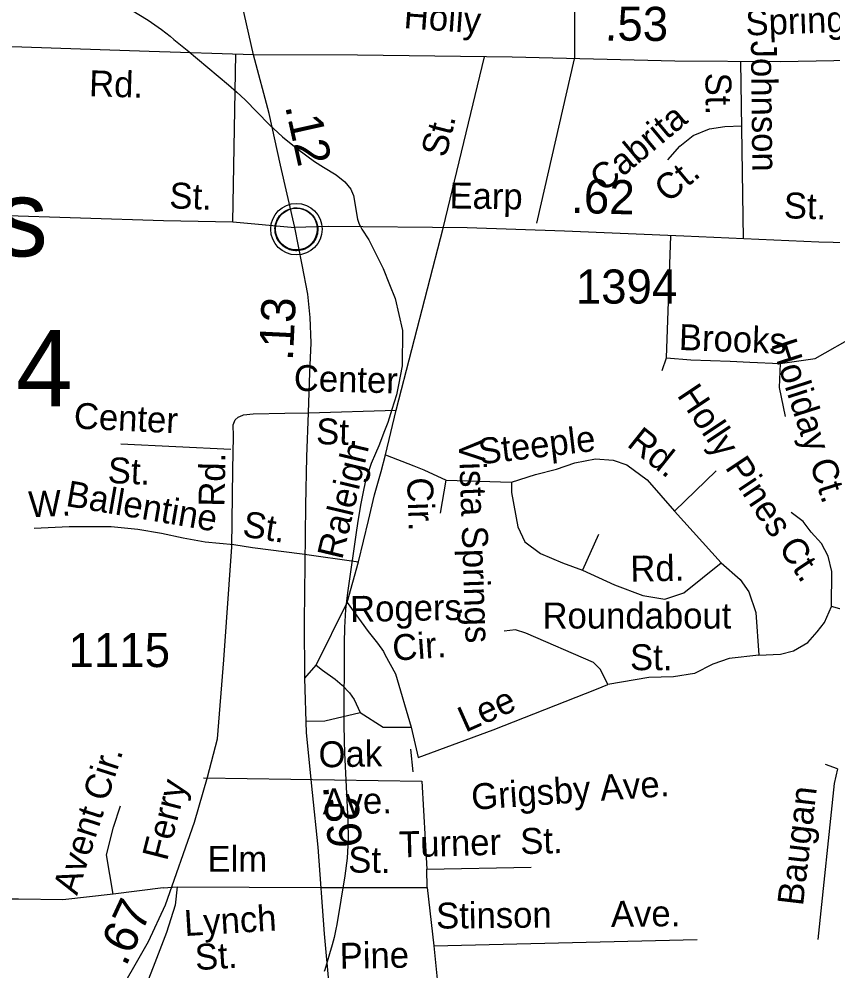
# Model space of a CAD drawing. Extents: x 2001466 to 2224147, y 644118 to 847247.
# Drawn here: x 2048372 to 2051357, y 689942 to 693432 of the extents above; entities that cross this region are included whole.
import ezdxf

# ---------------------------------------------------------------- set-up
doc = ezdxf.new("R2010")
doc.units = 0
for name, color, linetype in [('Exist Civil Demographics City Label', 7, 'Continuous'), ('Exist Civil Demographics Community CELL', 7, 'Continuous'), ('Exist Hydrographic Misc Water Feature', 7, 'Continuous'), ('Exist Road Non-System Type 51', 7, 'Continuous'), ('Exist Road Non-System Type 51 Label', 7, 'Continuous'), ('Exist Road Primary NC Attributed', 7, 'Continuous'), ('Exist Road Primary NC Service Mileage Hundredths English Label', 7, 'Continuous'), ('Exist Road Secondary Mileage Hundredths English Label', 7, 'Continuous'), ('Exist Road Secondary Type 51 Attributed', 7, 'Continuous'), ('Exist Road Secondary Type 51 Label', 7, 'Continuous'), ('Exist Road Secondary Type 51 Number Label', 7, 'Continuous')]:
    doc.layers.add(name, color=color, linetype=linetype)

msp = doc.modelspace()

# ---------------------------------------------------------------- linework, layer by layer
at = {"layer": 'Exist Civil Demographics Community CELL'}
msp.add_lwpolyline([(2049311.9, 692674.2), (2049312.9, 692679.8), (2049314.7, 692686.4), (2049317.6, 692693.6), (2049320.5, 692699.3), (2049323.9, 692705.1), (2049327.6, 692710.2), (2049331.6, 692714.6), (2049336.2, 692719.2), (2049341.7, 692723.7), (2049347.1, 692727.4), (2049352, 692730.3), (2049357.1, 692732.7), (2049362.5, 692735), (2049368.2, 692736.8), (2049372.5, 692738), (2049377.3, 692738.7), (2049381.5, 692739.5), (2049387.8, 692739.7), (2049392.3, 692739.6), (2049397.9, 692739.3), (2049402.8, 692738.6), (2049407.7, 692737.6), (2049412.8, 692736.2), (2049417.9, 692734.3), (2049424.6, 692731.4), (2049430.8, 692727.9), (2049435.9, 692724.3), (2049441.1, 692720.3), (2049444.4, 692717.2), (2049448.5, 692712.8), (2049452.4, 692708.1), (2049455.4, 692703.5), (2049458.6, 692698.5), (2049461, 692693.3), (2049463.1, 692688.3), (2049464.6, 692683.3), (2049465.9, 692678.7), (2049467, 692672.7), (2049467.6, 692668), (2049467.9, 692662), (2049467.7, 692656.2), (2049467.1, 692650.5), (2049466.2, 692645), (2049464.5, 692638.9), (2049462.7, 692633), (2049460.4, 692627.9), (2049457.2, 692621.9), (2049453.9, 692616.6), (2049450.5, 692611.9), (2049446.3, 692607.2), (2049441, 692602.2), (2049435.9, 692598.1), (2049430.9, 692594.7), (2049426.6, 692592.2), (2049419.8, 692588.9), (2049412.6, 692586.2), (2049406.7, 692584.7), (2049400.1, 692583.4), (2049395.7, 692583), (2049391.2, 692582.7), (2049385.6, 692582.7), (2049381.3, 692583.1), (2049375.7, 692583.9), (2049369.8, 692585.2), (2049365.2, 692586.5), (2049360, 692588.3), (2049355.4, 692590.3), (2049351.5, 692592.6), (2049344.7, 692596.6), (2049339.1, 692600.9), (2049334.2, 692605.4), (2049329.7, 692610.3), (2049326.6, 692614.2), (2049323.6, 692618.4), (2049319.5, 692625.5), (2049317.8, 692629), (2049316, 692633.1), (2049313.5, 692641.3), (2049311.9, 692648.3), (2049311.2, 692653.5), (2049310.9, 692659.8), (2049310.8, 692664.5), (2049311.4, 692670.9)], close=True, dxfattribs=at)
for centre, radius in [((2049389.5, 692661.8), 94.3), ((2049389.3, 692662.1), 76.7)]:
    msp.add_circle(centre, radius, dxfattribs=at)
at = {"layer": 'Exist Hydrographic Misc Water Feature'}
for p, q in [((2048783.2, 693465.6), (2048846.2, 693428.1)), ((2049567.1, 692835.3), (2049589.1, 692808.5)), ((2049589.1, 692808.5), (2049591.5, 692802.2)), ((2049589.1, 692808.5), (2049591.5, 692802.2)), ((2049493.1, 689947), (2049491.1, 689940.2))]:
    msp.add_line(p, q, dxfattribs=at)
for points in [[(2048846.2, 693428.1), (2048895.2, 693393.4), (2048926.1, 693368.7)], [(2048846.2, 693428.1), (2048895.2, 693393.4), (2048926.1, 693368.7)], [(2048926.1, 693368.7), (2048940.3, 693357.4), (2048988.3, 693317.4)], [(2048926.1, 693368.7), (2048940.3, 693357.4), (2048988.3, 693317.4)], [(2048988.3, 693317.4), (2049140.2, 693190.8), (2049170.6, 693163.6)], [(2048988.3, 693317.4), (2049140.2, 693190.8), (2049170.6, 693163.6)], [(2049170.6, 693163.6), (2049202.1, 693135.3), (2049290.1, 693045.7), (2049338.1, 693000.7), (2049394.1, 692954.5), (2049455.2, 692910.4), (2049488.4, 692889.6)], [(2049170.6, 693163.6), (2049202.1, 693135.3), (2049290.1, 693045.7), (2049338.1, 693000.7), (2049394.1, 692954.5), (2049455.2, 692910.4), (2049488.4, 692889.6)], [(2049488.4, 692889.6), (2049535.4, 692860.4), (2049567.1, 692835.3)], [(2049488.4, 692889.6), (2049535.4, 692860.4), (2049567.1, 692835.3)], [(2049591.5, 692802.2), (2049598.1, 692785.2), (2049613.1, 692698.6), (2049620, 692680.1), (2049623.9, 692672)], [(2049591.5, 692802.2), (2049598.1, 692785.2), (2049613.1, 692698.6), (2049620, 692680.1), (2049623.9, 692672)], [(2049623.9, 692672), (2049629.3, 692661.2), (2049655.1, 692622.6), (2049708, 692517), (2049730.8, 692459.1)], [(2049623.9, 692672), (2049629.3, 692661.2), (2049655.1, 692622.6), (2049708, 692517), (2049730.8, 692459.1)], [(2049730.8, 692459.1), (2049750.9, 692407.5), (2049778.1, 692289.8), (2049777.1, 692160.9), (2049763.4, 692090.5)], [(2049730.8, 692459.1), (2049750.9, 692407.5), (2049778.1, 692289.8), (2049777.1, 692160.9), (2049763.4, 692090.5)], [(2049763.4, 692090.5), (2049756.2, 692054.1), (2049739.8, 692000.8)], [(2049763.4, 692090.5), (2049756.2, 692054.1), (2049739.8, 692000.8)], [(2049739.8, 692000.8), (2049725, 691953.4), (2049712.9, 691922.8)], [(2049739.8, 692000.8), (2049725, 691953.4), (2049712.9, 691922.8)], [(2049712.9, 691922.8), (2049691, 691867), (2049678.9, 691839.4)], [(2049712.9, 691922.8), (2049691, 691867), (2049678.9, 691839.4)], [(2049678.9, 691839.4), (2049662.9, 691803), (2049643, 691738.9), (2049637.1, 691710.9)], [(2049678.9, 691839.4), (2049662.9, 691803), (2049643, 691738.9), (2049637.1, 691710.9)], [(2049637.1, 691710.9), (2049624.3, 691650.3), (2049613.3, 691582.9)], [(2049637.1, 691710.9), (2049624.3, 691650.3), (2049613.3, 691582.9)], [(2049613.3, 691582.9), (2049608.1, 691550.2), (2049576.2, 691328), (2049569, 691267.3)], [(2049613.3, 691582.9), (2049608.1, 691550.2), (2049576.2, 691328), (2049569, 691267.3)], [(2049569, 691267.3), (2049565.3, 691201.4), (2049564.1, 691143.5)], [(2049569, 691267.3), (2049565.3, 691201.4), (2049564.1, 691143.5)], [(2049564.1, 691143.5), (2049563, 690846.2), (2049564.3, 690786.5)], [(2049564.1, 691143.5), (2049563, 690846.2), (2049564.3, 690786.5)], [(2049564.3, 690786.5), (2049565.1, 690742.1), (2049578, 690493.2), (2049579, 690425.2), (2049575.1, 690355.9)], [(2049564.3, 690786.5), (2049565.1, 690742.1), (2049578, 690493.2), (2049579, 690425.2), (2049575.1, 690355.9)], [(2049575.1, 690355.9), (2049567.1, 690290.5), (2049537, 690112.1), (2049533.9, 690095.5)], [(2049575.1, 690355.9), (2049567.1, 690290.5), (2049537, 690112.1), (2049533.9, 690095.5)], [(2049533.9, 690095.5), (2049527.8, 690064.4), (2049520.4, 690038.2)], [(2049533.9, 690095.5), (2049527.8, 690064.4), (2049520.4, 690038.2)], [(2049520.4, 690038.2), (2049511.2, 690005.3), (2049493.1, 689947)], [(2049520.4, 690038.2), (2049511.2, 690005.3), (2049493.1, 689947)]]:
    msp.add_lwpolyline(points, dxfattribs=at)
at = {"layer": 'Exist Road Non-System Type 51'}
for p, q in [((2049155.7, 692688.3), (2049167.2, 693302.7)), ((2049927, 692665.2), (2050078.9, 693293.6)), ((2050270.5, 692684), (2050409.1, 693285.9)), ((2051028.9, 692626.3), (2051019.1, 693276.2)), ((2048200.1, 692715.7), (2048901.7, 692693.5)), ((2048901.7, 692693.5), (2049155.7, 692688.3)), ((2049155.7, 692688.3), (2049383.7, 692667.9)), ((2049755, 691998.3), (2049927, 692665.2)), ((2050745.8, 692189.6), (2050762.5, 692637.8)), ((2050730.3, 692143.2), (2050745.8, 692189.6)), ((2049433.8, 691988.7), (2049755, 691998.3)), ((2049715.6, 691834), (2049755, 691998.3)), ((2049148.4, 691854.4), (2048745.6, 691873.6)), ((2050928.8, 691775.5), (2050776, 691627.8)), ((2049918.2, 691620.9), (2049938.8, 691741.2)), ((2049938.8, 691741.2), (2050177.5, 691734.3)), ((2050776, 691627.8), (2050947.3, 691438.8)), ((2050496.8, 691541.9), (2050438.4, 691411.3)), ((2049054.7, 691515), (2049160, 691506.1)), ((2049411, 691471.5), (2049616.6, 691442.5)), ((2049575.5, 691293.6), (2049616.6, 691442.5)), ((2049462.2, 691063.4), (2049575.5, 691293.6)), ((2049420.1, 691015.9), (2049462.2, 691063.4)), ((2049809.7, 690836.6), (2049835.4, 690724.9)), ((2049817.9, 690672.3), (2049809, 690755.4)), ((2049049, 690650.3), (2049849.5, 690638.4)), ((2049849.5, 690638.4), (2049867.2, 690315)), ((2049867.2, 690315), (2050250.2, 690322.3)), ((2049869, 690248.6), (2049867.2, 690315)), ((2048901.1, 690247.5), (2048717.2, 690224.4)), ((2048901.1, 690247.5), (2048951.8, 690250.4)), ((2048951.8, 690250.4), (2049480.6, 690248.6)), ((2049480.6, 690248.6), (2049869, 690248.6)), ((2049869, 690248.6), (2049892.7, 690035)), ((2049892.7, 690035), (2050858.8, 690057.9)), ((2049892.7, 690035), (2049907, 689900.5))]:
    msp.add_line(p, q, dxfattribs=at)
for points in [[(2050407.2, 693733.7), (2050409.1, 693285.9)], [(2050750.9, 692916), (2050795.6, 692965.8), (2050843.6, 693005.3), (2050903.7, 693029.4), (2050960.4, 693038), (2051022.7, 693040.2)], [(2051163, 692169), (2051291.8, 692187.9), (2051446.3, 692275.5)], [(2050745.8, 692189.6), (2050835.1, 692182.7), (2050979.3, 692177.6), (2051051.4, 692174.1), (2051163, 692169)], [(2051163, 692169), (2051158.9, 692081.2), (2051181.2, 691974.7)], [(2049195.7, 691980.9), (2049230.4, 691984.2), (2049347.5, 691986.6), (2049433.8, 691988.7)], [(2049616.6, 691442.5), (2049654.3, 691593.2), (2049676.1, 691688.1), (2049700.2, 691773.8), (2049715.6, 691834)], [(2049715.6, 691834), (2049820.3, 691794.4), (2049856.4, 691779), (2049938.8, 691741.2)], [(2050177.5, 691734.3), (2050265.7, 691761.8), (2050343, 691782.4), (2050409.9, 691804.8), (2050485.5, 691820.2), (2050550.7, 691815.1), (2050600.5, 691797.9), (2050675.7, 691743.2), (2050776, 691627.8)], [(2050177.5, 691734.3), (2050178.2, 691696.5), (2050201.5, 691571.1), (2050227.3, 691516.1), (2050283.9, 691473.2), (2050364.6, 691438.8), (2050438.4, 691411.3)], [(2051350.7, 691278), (2051352.9, 691406.2), (2051339.2, 691462.9), (2051315.1, 691509.6), (2051277.3, 691550.5), (2051246.8, 691589.7), (2051203.5, 691622.6)], [(2048428.5, 691565.5), (2048556.1, 691571.4), (2048710.4, 691571.4), (2048808.3, 691562.5), (2048894.4, 691547.6), (2048974.5, 691529.8), (2049054.7, 691515)], [(2049160, 691506.1), (2049228.5, 691494.7), (2049411, 691471.5)], [(2051603.6, 691468), (2051614.8, 691367.1), (2051644.8, 691232.6), (2051548.6, 691224), (2051350.7, 691278)], [(2050438.4, 691411.3), (2050555.2, 691358.1), (2050659.9, 691318.5), (2050740.6, 691304.8), (2050809.3, 691328.8), (2050947.3, 691438.8)], [(2050947.3, 691438.8), (2051016, 691376.9), (2051048.6, 691332.3), (2051074.4, 691256.5), (2051084.7, 691100.2)], [(2049575.5, 691293.6), (2049652.8, 691187.1), (2049687.1, 691144.2), (2049708.9, 691113.7)], [(2051265, 691146.6), (2051299.3, 691186.1), (2051325.1, 691220.4), (2051350.7, 691278)], [(2050531.8, 690993), (2050504.6, 691047.9), (2050478.1, 691072.9), (2050231.1, 691180.8), (2050192.1, 691193.3), (2050151.4, 691188.6)], [(2051084.7, 691100.2), (2051163.7, 691103.6), (2051211.8, 691115.6), (2051265, 691146.6)], [(2049708.9, 691113.7), (2049714, 691102.8), (2049752.6, 691031.6), (2049809.7, 690836.6)], [(2051084.7, 691100.2), (2050976.5, 691087.5), (2050916.4, 691066.8), (2050849.5, 691032.5), (2050772.2, 691020.4), (2050681.2, 691018.7), (2050531.8, 690993)], [(2049462.2, 691063.4), (2049484.5, 691044.5), (2049530.9, 691011.9), (2049556.6, 690989.5)], [(2049556.6, 690989.5), (2049584.1, 690962), (2049601.3, 690938), (2049623.6, 690889.9)], [(2049835.4, 690724.9), (2050110.2, 690826.3), (2050489.6, 690975.8), (2050531.8, 690993)], [(2049425.1, 690857.6), (2049493.1, 690858.9), (2049623.6, 690889.9)], [(2049623.6, 690889.9), (2049707.7, 690836.6), (2049809.7, 690836.6)], [(2051373.6, 690683.1), (2051329.8, 690698.7)], [(2051373.6, 690683.1), (2051361.1, 690629.9), (2051301.7, 690057.5)], [(2048717.2, 690224.4), (2048533.2, 690202.6), (2048370.2, 690206.1), (2048284.1, 690206.1), (2048184.2, 690215.7), (2048123.9, 690238.7), (2048046.7, 690295.1), (2047871.3, 690433.1), (2047817.7, 690505.5), (2047779.6, 690598)], [(2048717.2, 690224.4), (2048692.6, 690368.6), (2048718.6, 690470), (2048744.7, 690548.3)], [(2048951.8, 690250.4), (2048944.6, 690183.1), (2048913.3, 690083.6), (2048864.7, 689956.6), (2048805.7, 689805.8), (2048676.7, 689466.4), (2048581.3, 689198.3), (2048529.2, 689063.3)]]:
    msp.add_lwpolyline(points, dxfattribs=at)
at = {"layer": 'Exist Road Primary NC Attributed'}
for points in [[(2049231.7, 693300.7), (2049181, 693529.9), (2049123.5, 693753.8), (2049079.7, 693939.7)], [(2049383.7, 692667.9), (2049331.4, 692896.1), (2049289.2, 693085.2), (2049231.7, 693300.7)], [(2049433.8, 691988.7), (2049438, 692136.6), (2049443.8, 692245.4), (2049439.6, 692338.4), (2049431.2, 692422.9), (2049410.1, 692530.6), (2049383.7, 692667.9)], [(2049509.3, 689892), (2049492.9, 690078.9), (2049469.2, 690395.8), (2049448.1, 690596.5), (2049426.4, 690815.2), (2049420.1, 691015.9), (2049418.5, 691224), (2049421.7, 691434.2), (2049423.8, 691648.6), (2049427.5, 691827.1), (2049433.8, 691988.7)]]:
    msp.add_lwpolyline(points, dxfattribs=at)
at = {"layer": 'Exist Road Secondary Type 51 Attributed'}
for points in [[(2049231.7, 693300.7), (2048849.5, 693312.9), (2048310.1, 693331.9), (2047902.1, 693338.2), (2047659.3, 693353), (2047450.3, 693384.7), (2047234.9, 693441.7), (2047002.7, 693498.8), (2046776.8, 693566.4), (2046644.8, 693625.5), (2046345, 693775.5), (2046100.1, 693885.4), (2045759.2, 694003.7), (2045468.9, 694106.2), (2045017.3, 694290.1)], [(2052012.7, 693290.6), (2051621.4, 693284.3), (2051163.8, 693275.6), (2050777.2, 693277.1), (2050180.8, 693292.1), (2049612.8, 693300), (2049231.7, 693300.7)], [(2052668.3, 692566.2), (2052428.5, 692571), (2051884.1, 692600.2), (2051305, 692614.4), (2050809.5, 692635.7), (2050372.5, 692654.7), (2050015.9, 692666.5), (2049506.2, 692671.2), (2049383.7, 692667.9)], [(2047871.5, 688899.5), (2048132.3, 689162.2), (2048336, 689402), (2048594.1, 689676.6), (2048716.6, 689821.3), (2048846.9, 690050.5), (2048909.2, 690184.7), (2049015.3, 690487.9), (2049063.9, 690652.6), (2049100.3, 690793.1), (2049123.5, 691082.6), (2049153.1, 691497.7), (2049155.7, 691779.7), (2049158.9, 691902.3), (2049157.3, 691944.9), (2049165.2, 691962.2), (2049175.4, 691972.4), (2049193.5, 691980.3), (2049195.7, 691980.9)]]:
    msp.add_lwpolyline(points, dxfattribs=at)

# ---------------------------------------------------------------- texts
at = {"layer": 'Exist Civil Demographics City Label'}
for s, p in [('Holly Springs', (2046272.2, 692562.3)), ('pop. 20,634', (2046591.3, 692012.3))]:
    msp.add_text(s, height=280, dxfattribs=at).set_placement(p)
at = {"layer": 'Exist Road Non-System Type 51 Label'}
for s, rotation, p in [('Johnson', 270.6614, (2051055.7, 693352.4)), ('St.', 270.6614, (2050888.8, 693235.1)), ('Cabrita', 39.8412, (2050515.2, 692793.7)), (' St.', 75.9235, (2049928.6, 692886.8)), ('Ct.', 39.8412, (2050751.7, 692755.3)), (' St.', 357.6631, (2048887, 692740.1)), ('Brooks', 357.8778, (2050790.5, 692219.1)), ('Holiday Ct.', 287.9206, (2051129.2, 692241.4)), ('Holly Pines Ct.', 303.6779, (2050782.5, 692053)), ('Center', 357.2595, (2048571.8, 691931.2)), ('Steeple', 6.7118, (2050062, 691799.1)), ('Rd.', 321.334, (2050597.3, 691869)), ('Vista Springs', 271.9747, (2049984.4, 691890.6)), ('Raleigh', 76.6582, (2049557, 691447.2)), ('St.', 357.2595, (2048696.2, 691731.6)), ('Ballentine', 350.2133, (2048540.4, 691647.5)), ('Cir.', 271.9747, (2049794.9, 691750.3)), ('W. ', 2.664, (2048409.2, 691605)), (' St.', 351.0895, (2049153.4, 691541.3)), ('Rd.', 0.9718, (2050614.5, 691369.6)), ('Rogers', 1.0364, (2049587, 691221.7)), ('Cir.', 4.0531, (2049744.4, 691079.3)), ('Lee', 24.1116, (2050008.9, 690815.2)), ('Oak', 1.0371, (2049471.5, 690688.4)), ('Avent Cir.', 72.2625, (2048585.2, 690216.7)), ('Grigsby Ave.', 4.025, (2050033.7, 690532.7)), ('Ferry', 75.7248, (2048914.8, 690342.7)), ('Ave.', 1.0371, (2049485.8, 690515.9)), ('Baugan', 83.2986, (2051246.6, 690178.6)), ('Turner  St.', 1.5462, (2049766.7, 690358.5)), (' St.', 359.4495, (2049543.9, 690303.6)), ('Stinson', 0.5756, (2049901.9, 690097.5)), ('Ave.', 0.5756, (2050543, 690104)), ('Lynch', 3.4745, (2048980.3, 690070.1)), ('St.', 3.4745, (2049020.2, 689945.1))]:
    msp.add_text(s, height=95, rotation=rotation, dxfattribs=at).set_placement(p)
for s, p in [('Roundabout', (2050291.8, 691197.7)), (' St.', (2050577.3, 691045)), ('Elm', (2049063.4, 690305.8))]:
    msp.add_text(s, height=95, dxfattribs=at).set_placement(p)
at = {"layer": 'Exist Road Primary NC Service Mileage Hundredths English Label'}
for s, rotation, p in [('.12', 282.5881, (2049347.1, 693112.5)), ('.13', 87.2159, (2049376.2, 692177.2)), ('.39', 274.9846, (2049486.6, 690620.2))]:
    msp.add_text(s, height=125, rotation=rotation, dxfattribs=at).set_placement(p)
at = {"layer": 'Exist Road Secondary Mileage Hundredths English Label'}
for s, rotation, p in [('.53', 359.5078, (2050519.5, 693353.4)), ('.62', 358.5165, (2050395.7, 692721.5)), ('.67', 65.0971, (2048764, 689955.6))]:
    msp.add_text(s, height=125, rotation=rotation, dxfattribs=at).set_placement(p)
at = {"layer": 'Exist Road Secondary Type 51 Label'}
for s, rotation, p in [('Holly', 355.8607, (2049780.9, 693398.9)), ('Springs', 2.1176, (2051037.5, 693371.4)), ('Rd.', 358.1999, (2048628.2, 693149.4)), ('Earp', 359.155, (2049950, 692737.9)), (' St.', 358.5165, (2051140.3, 692702.7)), ('Center', 358.4895, (2049378.9, 692069.6)), (' St.', 358.4895, (2049425.5, 691874.8)), ('Rd.', 88.8326, (2049125.4, 691643.5)), ('Pine', 1.0268, (2049548.8, 689950))]:
    msp.add_text(s, height=95, rotation=rotation, dxfattribs=at).set_placement(p)
at = {"layer": 'Exist Road Secondary Type 51 Number Label'}
for s, p in [('1394', (2050414, 692388.9)), ('1115', (2048554.3, 691056.4))]:
    msp.add_text(s, height=125, dxfattribs=at).set_placement(p)

doc.saveas('drawing.dxf')
